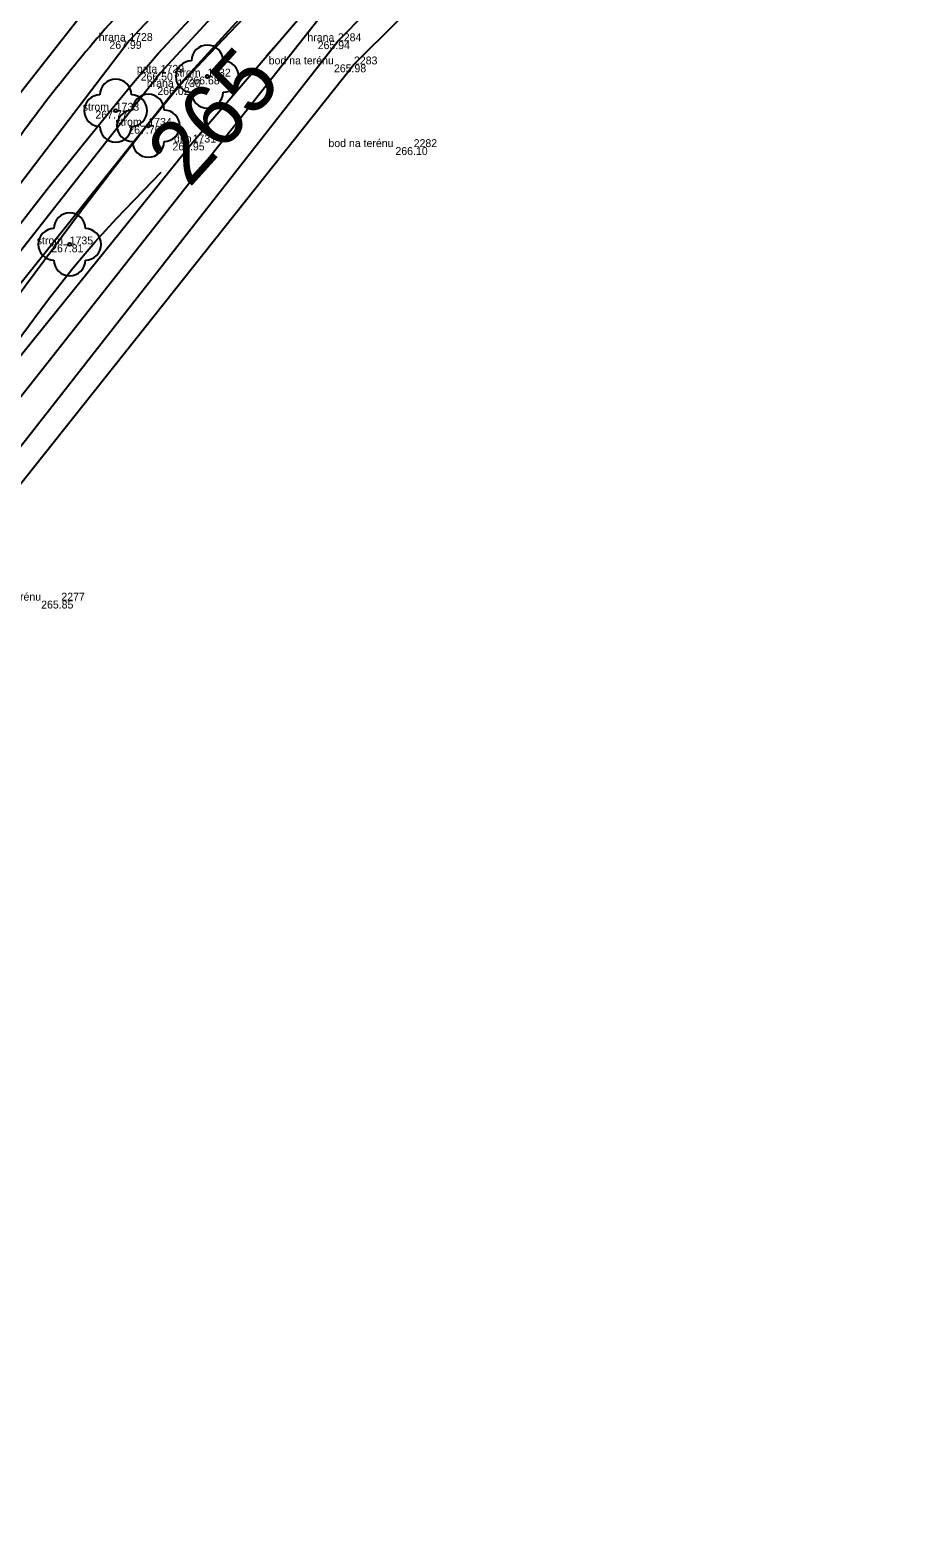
# Model space of a CAD drawing. Extents: x -567962 to -566460, y -1093720 to -1089838.
# Drawn here: x -566920.9 to -566865.9, y -1090322.4 to -1090226.7 of the extents above; entities that cross this region are included whole.
import ezdxf

# ---------------------------------------------------------------- set-up
doc = ezdxf.new("R2010")
doc.units = 0
for name, color, linetype in [('0_osa hráze', 7, 'Continuous'), ('bod_znacka', 7, 'Continuous'), ('cislo_bodu', 7, 'Continuous'), ('Doměření - kraj pole', 7, 'Continuous'), ('hlavni_vrst', 7, 'Continuous'), ('hrana_L', 7, 'Continuous'), ('hrana_P', 7, 'Continuous'), ('kod_bodu', 7, 'Continuous'), ('norm_vrst', 7, 'Continuous'), ('Popis_hl_vrs', 7, 'Continuous'), ('stromy', 7, 'Continuous'), ('vyska_bodu', 7, 'Continuous')]:
    doc.layers.add(name, color=color, linetype=linetype)

msp = doc.modelspace()

# ---------------------------------------------------------------- linework, layer by layer
at = {"layer": '0_osa hráze'}
msp.add_arc((-566843.631, -1090289.76), 96.141, 137.41218, 144.50722, dxfattribs=at)
at = {"layer": 'bod_znacka'}
for p, q in [((-566914.61, -1090227.38), (-566914.61, -1090227.38)), ((-566901.37, -1090227.4), (-566901.37, -1090227.4)), ((-566912.62, -1090229.4), (-566912.62, -1090229.4)), ((-566909.66, -1090229.64), (-566909.66, -1090229.64)), ((-566900.35, -1090228.87), (-566900.35, -1090228.87)), ((-566911.56, -1090230.31), (-566911.56, -1090230.31)), ((-566915.47, -1090231.81), (-566915.47, -1090231.81)), ((-566913.4, -1090232.77), (-566913.4, -1090232.77)), ((-566910.59, -1090233.83), (-566910.59, -1090233.83)), ((-566896.56, -1090234.12), (-566896.56, -1090234.12)), ((-566918.39, -1090240.3), (-566918.39, -1090240.3)), ((-566918.92, -1090262.92), (-566918.92, -1090262.92))]:
    msp.add_line(p, q, dxfattribs=at)
at = {"layer": 'Doměření - kraj pole'}
msp.add_lwpolyline([(-567047.906, -1090663.012), (-567047.627, -1090662.294), (-567014.86, -1090563.09), (-567002.362, -1090535.532), (-566955.49, -1090317.15), (-566941.63, -1090287.13), (-566940.57, -1090285.53), (-566924.46, -1090259.19), (-566900.35, -1090228.87), (-566877.72, -1090206.37), (-566851.19, -1090186.75), (-566766.44, -1090128.68), (-566717.21, -1090096.34), (-566711.98, -1090092.48)], dxfattribs=at)
at = {"layer": 'hlavni_vrst'}
for points in [[(-566905.915, -1090228.339), (-566905.444, -1090227.807)], [(-566921.855, -1090246.641), (-566919.79, -1090243.854), (-566918.972, -1090242.794), (-566918.183, -1090241.805), (-566917.414, -1090240.883), (-566916.77, -1090240.134), (-566915.419, -1090238.649), (-566912.577, -1090235.72)]]:
    msp.add_lwpolyline(points, dxfattribs=at)
at = {"layer": 'hrana_L'}
for p, q in [((-566892.08, -1090203.15), (-566914.61, -1090227.38)), ((-566890.38, -1090205.24), (-566912.62, -1090229.4)), ((-566911.56, -1090230.31), (-566889.6, -1090206.14)), ((-566932.7, -1090244.91), (-566917.27, -1090225.23)), ((-566914.61, -1090227.38), (-566929.58, -1090247.01)), ((-566912.62, -1090229.4), (-566928.62, -1090249.76)), ((-566927.33, -1090250.04), (-566911.56, -1090230.31))]:
    msp.add_line(p, q, dxfattribs=at)
for points in [[(-567053.87, -1090661.84), (-567020.06, -1090563.34), (-567005.258, -1090534.966), (-566958.763, -1090315.674), (-566944.67, -1090284.66), (-566926.49, -1090256.26), (-566902.65, -1090226.03), (-566881.28, -1090203.14), (-566853.44, -1090182.668), (-566715.257, -1090089.634)], [(-567050.54, -1090661.95), (-567017.83, -1090562.99), (-567002.61, -1090535.52), (-566957.72, -1090316.45), (-566942.31, -1090285.07), (-566925.11, -1090257.71), (-566901.37, -1090227.4), (-566879.5, -1090205.23), (-566852.16, -1090184), (-566767.57, -1090126.99), (-566713.28, -1090090.76)]]:
    msp.add_lwpolyline(points, dxfattribs=at)
at = {"layer": 'hrana_P'}
for p, q in [((-566910.59, -1090233.83), (-566888.71, -1090208.22)), ((-566922.79, -1090248.95), (-566910.59, -1090233.83))]:
    msp.add_line(p, q, dxfattribs=at)
at = {"layer": 'norm_vrst'}
for points in [[(-566922.93, -1090245.222), (-566917.696, -1090238.209), (-566915.578, -1090235.419), (-566913.546, -1090232.815), (-566911.613, -1090230.434), (-566911.335, -1090230.124), (-566909.945, -1090228.646), (-566906.461, -1090224.978)], [(-566921.513, -1090238.972), (-566920.65, -1090237.841), (-566919.678, -1090236.601), (-566917.517, -1090233.906), (-566915.218, -1090231.079), (-566914.241, -1090229.894), (-566912.766, -1090228.176), (-566909.871, -1090225.056)]]:
    msp.add_lwpolyline(points, dxfattribs=at)
at = {"layer": 'stromy'}
for centre in [(-566909.66, -1090229.64), (-566915.47, -1090231.81), (-566913.4, -1090232.77), (-566918.39, -1090240.3)]:
    msp.add_circle(centre, 0.1, dxfattribs=at)
for centre, start, end in [((-566909.66, -1090228.64), 0, 180), ((-566910.66, -1090229.64), 90, 270), ((-566908.66, -1090229.64), 270, 90), ((-566915.47, -1090230.81), 0, 180), ((-566916.47, -1090231.81), 90, 270), ((-566914.47, -1090231.81), 270, 90), ((-566913.4, -1090231.77), 0, 180), ((-566909.66, -1090230.64), 180, 0), ((-566914.4, -1090232.77), 90, 270), ((-566912.4, -1090232.77), 270, 90), ((-566915.47, -1090232.81), 180, 0), ((-566913.4, -1090233.77), 180, 0), ((-566918.39, -1090239.3), 0, 180), ((-566919.39, -1090240.3), 90, 270), ((-566917.39, -1090240.3), 270, 90), ((-566918.39, -1090241.3), 180, 0)]:
    msp.add_arc(centre, 1, start, end, dxfattribs=at)

# ---------------------------------------------------------------- texts
at = {"layer": 'cislo_bodu'}
for s, p in [('1728', (-566914.61, -1090227.38)), ('2284', (-566901.37, -1090227.4)), ('2283', (-566900.35, -1090228.87)), ('1729', (-566912.62, -1090229.4)), ('1732', (-566909.66, -1090229.64)), ('1730', (-566911.56, -1090230.31)), ('1733', (-566915.47, -1090231.81)), ('1734', (-566913.4, -1090232.77)), ('1731', (-566910.59, -1090233.83)), ('2282', (-566896.56, -1090234.12)), ('1735', (-566918.39, -1090240.3)), ('2277', (-566918.92, -1090262.92))]:
    msp.add_text(s, height=0.5, dxfattribs=at).set_placement(p)
at = {"layer": 'kod_bodu'}
for s, p in [('hrana', (-566916.547, -1090227.38)), ('hrana', (-566903.307, -1090227.4)), ('bod na terénu', (-566905.759, -1090228.87)), ('pata', (-566914.132, -1090229.4)), ('strom', (-566911.754, -1090229.64)), ('hrana', (-566913.497, -1090230.31)), ('strom', (-566917.564, -1090231.81)), ('strom', (-566915.494, -1090232.77)), ('dno', (-566911.771, -1090233.83)), ('bod na terénu', (-566901.969, -1090234.12)), ('strom', (-566920.484, -1090240.3)), ('bod na terénu', (-566924.329, -1090262.92))]:
    msp.add_text(s, height=0.5, dxfattribs=at).set_placement(p)
at = {"layer": 'Popis_hl_vrs'}
msp.add_text('265', height=4, rotation=47.9985, dxfattribs=at).set_placement((-566910.812, -1090236.771))
at = {"layer": 'vyska_bodu'}
for s, p in [('267.99', (-566915.87, -1090227.88)), ('265.94', (-566902.651, -1090227.9)), ('266.50', (-566913.888, -1090229.9)), ('266.68', (-566910.918, -1090230.14)), ('265.98', (-566901.62, -1090229.37)), ('266.02', (-566912.828, -1090230.81)), ('267.77', (-566916.757, -1090232.31)), ('267.76', (-566914.673, -1090233.27)), ('264.95', (-566911.871, -1090234.33)), ('266.10', (-566897.719, -1090234.62)), ('267.81', (-566919.565, -1090240.8)), ('265.85', (-566920.201, -1090263.42))]:
    msp.add_text(s, height=0.5, dxfattribs=at).set_placement(p)

doc.saveas('drawing.dxf')
